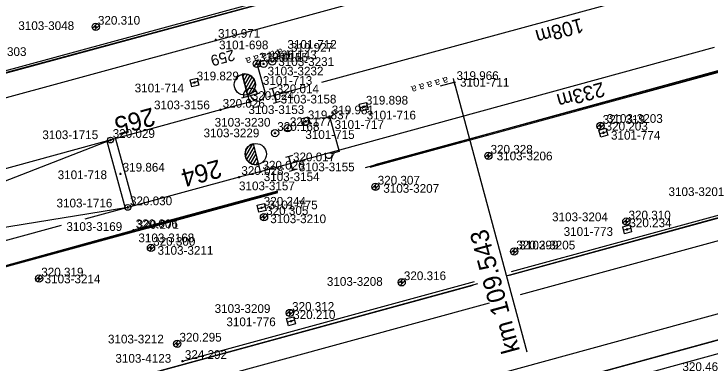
# Model space of a CAD drawing. Extents: x -821875 to -821475, y -1070280 to -1069975.
# Drawn here: x -821621.48 to -821573.63, y -1070227.07 to -1070203.07 of the extents above; entities that cross this region are included whole.
import ezdxf

# ---------------------------------------------------------------- set-up
doc = ezdxf.new("R2010")
doc.units = 0
for name, color, linetype in [('Vrstva 1', 7, 'Continuous'), ('Vrstva 14', 7, 'Continuous'), ('Vrstva 2', 7, 'Continuous'), ('Vrstva 23', 7, 'Continuous'), ('Vrstva 25', 7, 'Continuous'), ('Vrstva 28', 7, 'Continuous'), ('Vrstva 3', 7, 'Continuous'), ('Vrstva 36', 7, 'Continuous'), ('Vrstva 41', 7, 'Continuous'), ('Vrstva 43', 7, 'Continuous'), ('Vrstva 6', 7, 'Continuous'), ('Vrstva 60', 7, 'Continuous'), ('Vrstva 61', 7, 'Continuous'), ('Vrstva 7', 7, 'Continuous')]:
    doc.layers.add(name, color=color, linetype=linetype)

# ---------------------------------------------------------------- blocks, each defined once
blk = doc.blocks.new('BOD')
at = {"layer": 'Vrstva 3'}
for p, q in [((-0.15, 0), (0.15, 0)), ((0, -0.15), (0, 0.15))]:
    blk.add_line(p, q, dxfattribs=at)

msp = doc.modelspace()

# ---------------------------------------------------------------- linework, layer by layer
at = {"layer": 'Vrstva 1'}
for p, q in [((-821579.336, -1070202.053), (-821600.342, -1070207.794)), ((-821573.357, -1070205.377), (-821602.448, -1070213.353)), ((-821601.401, -1070208.083), (-821603.562, -1070208.674)), ((-821566.968, -1070216.997), (-821586.693, -1070222.375)), ((-821568.932, -1070222.548), (-821610.421, -1070233.913)), ((-821588.818, -1070222.954), (-821613.034, -1070229.557))]:
    msp.add_line(p, q, dxfattribs=at)
for points in [[(-821591.155, -1070200.399), (-821624.302, -1070209.451)], [(-821603.562, -1070208.674), (-821604.031, -1070208.8)], [(-821605.117, -1070209.091), (-821605.28, -1070209.135)], [(-821602.448, -1070213.353), (-821604.545, -1070213.921)]]:
    msp.add_lwpolyline(points, dxfattribs=at)
msp.add_spline([(-821500, -1070224.932), (-821542.652, -1070236.59), (-821589.48, -1070249.332)], degree=3, dxfattribs=at)
at = {"layer": 'Vrstva 14'}
for p, q in [((-821626.102, -1070208.071), (-821552.45, -1070188.031)), ((-821587.282, -1070220.776), (-821500, -1070196.987)), ((-821572.64, -1070206.994), (-821597.005, -1070213.634)), ((-821603.365, -1070215.368), (-821645.213, -1070226.773)), ((-821609.88, -1070226.935), (-821589.826, -1070221.469)), ((-821567.723, -1070224.034), (-821612.131, -1070236.166)), ((-821567.873, -1070224.036), (-821612.125, -1070236.188))]:
    msp.add_line(p, q, dxfattribs=at)
for points in [[(-821587.424, -1070221.035), (-821566.902, -1070215.424), (-821519.308, -1070202.358), (-821500, -1070197.087)], [(-821500, -1070197.101), (-821519.046, -1070202.296), (-821566.74, -1070215.352), (-821587.58, -1070221.064)], [(-821625.477, -1070208.02), (-821593.697, -1070199.421)], [(-821593.592, -1070199.416), (-821624.886, -1070207.92)], [(-821572.675, -1070206.874), (-821597.33, -1070213.642)], [(-821572.691, -1070206.915), (-821596.666, -1070213.434)], [(-821603.362, -1070215.255), (-821613.257, -1070217.946)], [(-821603.351, -1070215.295), (-821613.18, -1070217.993)], [(-821613.18, -1070217.993), (-821645.432, -1070226.806)], [(-821645.149, -1070226.747), (-821613.257, -1070217.946)], [(-821589.624, -1070221.624), (-821615.371, -1070228.68), (-821615.366, -1070228.674), (-821589.911, -1070221.714)]]:
    msp.add_lwpolyline(points, dxfattribs=at)
at = {"layer": 'Vrstva 2'}
for p, q in [((-821605.415, -1070208.638), (-821605.794, -1070207.225)), ((-821605.794, -1070207.225), (-821605.415, -1070208.638)), ((-821605.745, -1070207.408), (-821605.626, -1070207.202)), ((-821605.676, -1070207.665), (-821605.422, -1070207.225)), ((-821605.607, -1070207.92), (-821605.246, -1070207.295)), ((-821605.539, -1070208.177), (-821605.095, -1070207.408)), ((-821605.47, -1070208.433), (-821604.97, -1070207.568)), ((-821605.362, -1070208.62), (-821604.886, -1070207.798)), ((-821605.415, -1070208.638), (-821605.415, -1070208.638)), ((-821605.415, -1070208.639), (-821605.28, -1070209.135)), ((-821605.566, -1070212.867), (-821605.051, -1070212.005)), ((-821605.542, -1070212.467), (-821605.391, -1070212.213)), ((-821605.48, -1070213.085), (-821604.972, -1070212.233)), ((-821605.032, -1070211.999), (-821604.673, -1070213.418)), ((-821605.032, -1070211.999), (-821605.032, -1070211.999)), ((-821605.032, -1070212.003), (-821604.672, -1070213.422)), ((-821605.356, -1070213.238), (-821604.908, -1070212.487)), ((-821605.206, -1070213.347), (-821604.844, -1070212.741)), ((-821605.031, -1070213.416), (-821604.78, -1070212.995)), ((-821604.829, -1070213.438), (-821604.716, -1070213.249)), ((-821604.673, -1070213.423), (-821604.545, -1070213.921))]:
    msp.add_line(p, q, dxfattribs=at)
for points in [[(-821605.28, -1070209.135), (-821607.281, -1070209.67), (-821628.619, -1070215.518)], [(-821614.838, -1070211.741), (-821625.745, -1070215.999)], [(-821604.545, -1070213.921), (-821605.999, -1070214.289), (-821616.597, -1070217.171)], [(-821613.652, -1070216.37), (-821626.237, -1070218.411)], [(-821618.237, -1070217.617), (-821628.568, -1070220.426)]]:
    msp.add_lwpolyline(points, dxfattribs=at)
for centre, radius in [((-821605.605, -1070207.928), 0.731), ((-821614.838, -1070211.741), 0.2), ((-821604.853, -1070212.709), 0.731), ((-821613.652, -1070216.37), 0.2)]:
    msp.add_circle(centre, radius, dxfattribs=at)
for centre, start, end in [((-821605.604, -1070207.932), 285.0402, 105.0011), ((-821604.853, -1070212.709), 104.2429, 284.2038)]:
    msp.add_arc(centre, 0.732, start, end, dxfattribs=at)
at = {"layer": 'Vrstva 23'}
msp.add_lwpolyline([(-821579.481, -1070228.171), (-821564.133, -1070223.955)], dxfattribs=at)
at = {"layer": 'Vrstva 25'}
for p, q in [((-821604.72, -1070206.257), (-821604.956, -1070206.674)), ((-821604.566, -1070206.366), (-821604.783, -1070206.749)), ((-821604.71, -1070206.741), (-821604.243, -1070208.428)), ((-821604.58, -1070208.521), (-821605.834, -1070208.868))]:
    msp.add_line(p, q, dxfattribs=at)
msp.add_circle((-821604.777, -1070206.5), 0.25, dxfattribs=at)
msp.add_circle((-821604.777, -1070206.5), 0.25, dxfattribs=at)
for centre, start, end in [((-821605.209, -1070208.688), 14.7707, 196.1758), ((-821604.725, -1070208.561), 195.4732, 15.4732)]:
    msp.add_arc(centre, 0.5, start, end, dxfattribs=at)
at = {"layer": 'Vrstva 28'}
for p, q in [((-821604.339, -1070206.501), (-821604.289, -1070206.501)), ((-821603.747, -1070206.342), (-821603.697, -1070206.342)), ((-821602.685, -1070210.933), (-821602.635, -1070210.933)), ((-821603.554, -1070211.261), (-821603.504, -1070211.261))]:
    msp.add_line(p, q, dxfattribs=at)
for centre in [(-821603.722, -1070206.342), (-821604.314, -1070206.501), (-821602.66, -1070210.933), (-821603.529, -1070211.261)]:
    msp.add_circle(centre, 0.25, dxfattribs=at)
at = {"layer": 'Vrstva 3'}
for p, q in [((-821603.454, -1070208.125), (-821603.936, -1070208.258)), ((-821603.429, -1070209.156), (-821603.695, -1070208.192)), ((-821603.188, -1070209.09), (-821603.67, -1070209.223)), ((-821602.339, -1070212.804), (-821602.822, -1070212.937)), ((-821602.316, -1070213.835), (-821602.58, -1070212.871)), ((-821602.074, -1070213.769), (-821602.557, -1070213.902))]:
    msp.add_line(p, q, dxfattribs=at)
at = {"layer": 'Vrstva 36'}
for p, q in [((-821616.084, -1070204.056), (-821615.762, -1070203.733)), ((-821615.954, -1070204.191), (-821615.627, -1070203.864)), ((-821581.388, -1070210.863), (-821581.066, -1070210.54)), ((-821581.258, -1070210.998), (-821580.931, -1070210.67)), ((-821589.098, -1070212.92), (-821588.776, -1070212.597)), ((-821588.968, -1070213.055), (-821588.641, -1070212.728)), ((-821596.854, -1070215.044), (-821596.532, -1070214.721)), ((-821596.724, -1070215.179), (-821596.397, -1070214.852)), ((-821604.52, -1070217.131), (-821604.198, -1070216.808)), ((-821604.39, -1070217.266), (-821604.063, -1070216.938)), ((-821579.614, -1070217.438), (-821579.292, -1070217.115)), ((-821579.484, -1070217.573), (-821579.157, -1070217.246)), ((-821612.288, -1070219.247), (-821611.964, -1070218.924)), ((-821612.158, -1070219.382), (-821611.83, -1070219.054)), ((-821587.33, -1070219.497), (-821587.008, -1070219.174)), ((-821587.2, -1070219.632), (-821586.873, -1070219.304)), ((-821619.98, -1070221.357), (-821619.656, -1070221.034)), ((-821619.85, -1070221.492), (-821619.522, -1070221.164)), ((-821595.056, -1070221.612), (-821594.732, -1070221.289)), ((-821594.926, -1070221.747), (-821594.598, -1070221.42)), ((-821602.74, -1070223.719), (-821602.418, -1070223.396)), ((-821602.61, -1070223.854), (-821602.283, -1070223.526)), ((-821610.478, -1070225.836), (-821610.156, -1070225.513)), ((-821610.348, -1070225.971), (-821610.021, -1070225.644))]:
    msp.add_line(p, q, dxfattribs=at)
for centre in [(-821615.854, -1070203.964), (-821581.158, -1070210.771), (-821588.868, -1070212.828), (-821596.624, -1070214.952), (-821604.29, -1070217.039), (-821579.384, -1070217.346), (-821612.057, -1070219.155), (-821587.1, -1070219.405), (-821619.749, -1070221.265), (-821594.825, -1070221.52), (-821602.51, -1070223.627), (-821610.248, -1070225.744)]:
    msp.add_circle(centre, 0.25, dxfattribs=at)
at = {"layer": 'Vrstva 41'}
for p, q in [((-821599.541, -1070210.057), (-821600.023, -1070210.191)), ((-821599.782, -1070210.124), (-821599.116, -1070212.534)), ((-821599.116, -1070212.534), (-821599.597, -1070212.667))]:
    msp.add_line(p, q, dxfattribs=at)
msp.add_arc((-821599.837, -1070212.738), 0.25, 194.308, 16.5996, dxfattribs=at)
at = {"layer": 'Vrstva 43'}
for points in [[(-821608.826, -1070207.722), (-821608.76, -1070207.962), (-821609.241, -1070208.095), (-821609.374, -1070207.614), (-821608.893, -1070207.481), (-821608.826, -1070207.722), (-821609.308, -1070207.854)], [(-821597.196, -1070209.391), (-821597.131, -1070209.632), (-821597.613, -1070209.762), (-821597.743, -1070209.28), (-821597.261, -1070209.15), (-821597.196, -1070209.391), (-821597.678, -1070209.521)], [(-821601.182, -1070210.396), (-821601.118, -1070210.638), (-821601.601, -1070210.767), (-821601.73, -1070210.284), (-821601.247, -1070210.155), (-821601.182, -1070210.396), (-821601.666, -1070210.526)], [(-821580.718, -1070211.172), (-821580.652, -1070211.413), (-821581.134, -1070211.545), (-821581.266, -1070211.063), (-821580.784, -1070210.931), (-821580.718, -1070211.172), (-821581.2, -1070211.304)], [(-821604.215, -1070216.337), (-821604.15, -1070216.578), (-821604.633, -1070216.707), (-821604.762, -1070216.224), (-821604.279, -1070216.095), (-821604.215, -1070216.337), (-821604.697, -1070216.465)], [(-821579.085, -1070217.814), (-821579.019, -1070218.056), (-821579.502, -1070218.187), (-821579.633, -1070217.704), (-821579.15, -1070217.573), (-821579.085, -1070217.814), (-821579.567, -1070217.946)], [(-821602.191, -1070224.128), (-821602.125, -1070224.37), (-821602.608, -1070224.501), (-821602.739, -1070224.018), (-821602.256, -1070223.887), (-821602.191, -1070224.128), (-821602.673, -1070224.26)]]:
    msp.add_lwpolyline(points, dxfattribs=at)
at = {"layer": 'Vrstva 6'}
for p, q in [((-821602.521, -1070206.065), (-821602.649, -1070205.583)), ((-821603.542, -1070206.079), (-821602.585, -1070205.824)), ((-821591.144, -1070208.005), (-821591.274, -1070207.523)), ((-821592.164, -1070208.023), (-821591.209, -1070207.764)), ((-821591.209, -1070207.764), (-821586.214, -1070226.287))]:
    msp.add_line(p, q, dxfattribs=at)
at = {"layer": 'Vrstva 7'}
for p, q in [((-821615.081, -1070211.808), (-821613.823, -1070216.417)), ((-821614.502, -1070211.649), (-821613.244, -1070216.259))]:
    msp.add_line(p, q, dxfattribs=at)

# ---------------------------------------------------------------- block references
at = {"layer": 'Vrstva 60', "xscale": 0.5, "yscale": 0.5}
for p in [(-821615.854, -1070203.964), (-821607.598, -1070204.862), (-821602.585, -1070205.824), (-821604.777, -1070206.5), (-821604.314, -1070206.501), (-821603.722, -1070206.342), (-821609.067, -1070207.788), (-821591.209, -1070207.764), (-821605.28, -1070209.135), (-821603.562, -1070208.674), (-821597.437, -1070209.456), (-821607.281, -1070209.67), (-821601.424, -1070210.461), (-821599.782, -1070210.124), (-821602.66, -1070210.933), (-821581.158, -1070210.771), (-821603.529, -1070211.261), (-821580.959, -1070211.238), (-821614.838, -1070211.741), (-821588.868, -1070212.828), (-821602.448, -1070213.353), (-821614.155, -1070214.062), (-821605.999, -1070214.289), (-821604.545, -1070213.921), (-821596.624, -1070214.952), (-821613.652, -1070216.37), (-821604.456, -1070216.401), (-821604.29, -1070217.039), (-821579.384, -1070217.346), (-821613.257, -1070217.946), (-821613.18, -1070217.993), (-821579.326, -1070217.88), (-821612.057, -1070219.155), (-821587.1, -1070219.405), (-821619.749, -1070221.265), (-821594.825, -1070221.52), (-821602.51, -1070223.627), (-821602.432, -1070224.194), (-821610.248, -1070225.744), (-821609.88, -1070226.935)]:
    msp.add_blockref('BOD', p, dxfattribs=at)

# ---------------------------------------------------------------- texts
at = {"layer": 'Vrstva 1'}
for s, rotation, p in [('108m', 195.2241, (-821582.491, -1070203.339)), ('233m', 195.3482, (-821581.027, -1070207.739))]:
    msp.add_text(s, height=1, rotation=rotation, dxfattribs=at).set_placement(p)
at = {"layer": 'Vrstva 2'}
for s, rotation, p in [('265', 195.3259, (-821611.98, -1070209.489)), ('264', 195.2126, (-821607.399, -1070213.06))]:
    msp.add_text(s, height=1.25, rotation=rotation, dxfattribs=at).set_placement(p)
at = {"layer": 'Vrstva 25'}
msp.add_text('259', height=0.75, rotation=195.4731, dxfattribs=at).set_placement((-821606.411, -1070205.514))
at = {"layer": 'Vrstva 6'}
for s, height, rotation, p in [('  a a a a a', 0.5, 194.9161, (-821602.713, -1070205.341)), ('  a a a a a', 0.5, 195.1747, (-821591.34, -1070207.281)), ('km 109.543', 1.25, 105.0929, (-821586.687, -1070226.219))]:
    msp.add_text(s, height=height, rotation=rotation, dxfattribs=at).set_placement(p)
at = {"layer": 'Vrstva 60'}
for s, p in [('3103-3048', (-821621.175, -1070204.181)), ('3101-698', (-821607.378, -1070205.505)), ('3101-712', (-821602.68, -1070205.468)), ('3103-3231', (-821603.308, -1070206.652)), ('3103-3232', (-821604.041, -1070207.301)), ('3101-713', (-821604.365, -1070207.948)), ('3101-711', (-821590.814, -1070208.074)), ('3101-714', (-821613.178, -1070208.465)), ('3103-3156', (-821611.848, -1070209.63)), ('3103-3158', (-821603.149, -1070209.229)), ('3103-3153', (-821605.358, -1070209.953)), ('3101-716', (-821597.234, -1070210.326)), ('3103-3203', (-821580.718, -1070210.561)), ('3103-3230', (-821607.683, -1070210.823)), ('3101-717', (-821599.438, -1070210.976)), ('3103-3229', (-821608.445, -1070211.554)), ('3103-1715', (-821619.523, -1070211.678)), ('3101-715', (-821601.45, -1070211.664)), ('3101-774', (-821580.439, -1070211.714)), ('3103-3206', (-821588.297, -1070213.138)), ('3103-3155', (-821601.895, -1070213.89)), ('3101-718', (-821618.469, -1070214.428)), ('3103-3154', (-821604.307, -1070214.564)), ('3103-3157', (-821606.007, -1070215.194)), ('3103-3207', (-821596.089, -1070215.366)), ('3103-3201', (-821576.485, -1070215.591)), ('3103-1716', (-821618.548, -1070216.372)), ('3101-775', (-821603.991, -1070216.501)), ('3103-3204', (-821584.489, -1070217.322)), ('3103-3210', (-821603.859, -1070217.454)), ('3103-3169', (-821617.872, -1070217.987)), ('3101-773', (-821583.692, -1070218.33)), ('3103-3168', (-821612.923, -1070218.766)), ('3103-3211', (-821611.605, -1070219.626)), ('3103-3205', (-821586.735, -1070219.261)), ('3103-3214', (-821619.368, -1070221.587)), ('3103-3208', (-821599.967, -1070221.762)), ('3103-3209', (-821607.685, -1070223.625)), ('3101-776', (-821606.874, -1070224.536)), ('3103-3212', (-821615.014, -1070225.72)), ('3103-4123', (-821614.502, -1070227.047))]:
    msp.add_text(s, height=0.6, dxfattribs=at).set_placement(p)
at = {"layer": 'Vrstva 61'}
for s, p in [('320.310', (-821615.704, -1070203.814)), ('319.971', (-821607.448, -1070204.712)), ('319.927', (-821602.435, -1070205.674)), ('320.303', (-821623.515, -1070205.965)), ('320.143', (-821603.572, -1070206.192)), ('319.811', (-821604.627, -1070206.35)), ('320.155', (-821604.164, -1070206.351)), ('319.829', (-821608.917, -1070207.638)), ('319.966', (-821591.059, -1070207.614)), ('320.014', (-821603.412, -1070208.524)), ('320.024', (-821605.13, -1070208.985)), ('320.026', (-821607.131, -1070209.52)), ('319.898', (-821597.287, -1070209.306)), ('319.981', (-821599.632, -1070209.974)), ('319.837', (-821601.274, -1070210.311)), ('320.319', (-821581.008, -1070210.621)), ('320.177', (-821602.51, -1070210.783)), ('320.203', (-821580.809, -1070211.088)), ('320.168', (-821603.379, -1070211.111)), ('320.029', (-821614.688, -1070211.591)), ('320.328', (-821588.718, -1070212.678)), ('320.017', (-821602.298, -1070213.203)), ('319.864', (-821614.005, -1070213.912)), ('320.026', (-821604.395, -1070213.771)), ('320.028', (-821605.849, -1070214.139)), ('320.307', (-821596.474, -1070214.802)), ('320.030', (-821613.502, -1070216.22)), ('320.244', (-821604.306, -1070216.251)), ('320.305', (-821604.14, -1070216.889)), ('320.310', (-821579.234, -1070217.196)), ('320.006', (-821613.107, -1070217.796)), ('320.234', (-821579.176, -1070217.73)), ('320.271', (-821613.03, -1070217.843)), ('320.300', (-821611.907, -1070219.005)), ('320.299', (-821586.95, -1070219.255)), ('320.319', (-821619.599, -1070221.115)), ('320.316', (-821594.675, -1070221.37)), ('320.312', (-821602.36, -1070223.477)), ('320.210', (-821602.282, -1070224.044)), ('320.295', (-821610.098, -1070225.594)), ('324.292', (-821609.73, -1070226.785)), ('320.465', (-821575.531, -1070227.616))]:
    msp.add_text(s, height=0.6, dxfattribs=at).set_placement(p)

doc.saveas('drawing.dxf')
